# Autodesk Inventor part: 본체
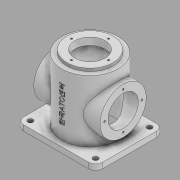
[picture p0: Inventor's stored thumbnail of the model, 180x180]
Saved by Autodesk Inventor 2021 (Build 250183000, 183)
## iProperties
Created: 2021-02
Part Number: 본체
Material: 알루미늄 6061
Document SubType Name: Modeling
Designer: 201-25
Density: 2.7 g/cm^3
Appearance: 기본값
Mass: 1239.52 g
Surface Area: 1098.82 cm^2
Volume: 459.08 cm^3
Author: 201-25
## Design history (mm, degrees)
sketch "스케치1"
  geometry: L1 (70, 60)-(-70, 60); L2 (-70, 60)-(-70, -60); L3 (-70, -60)-(70, -60); L4 (70, -60)-(70, 60); L5 (70, 60)-(-70, -60); L6 (-70, 60)-(70, -60); 1 further point
  constraints: 12 end point, 2 midpoint, 2 parallel, 1 horizontal, 1 perpendicular
  dimensions: "d0" = 140 distance of L3.end L2.end; "d1" = 120 distance of L2.end L1.end
extrude "돌출1" new body sketch "스케치1" distance "d2" = 10; taper "d3" = 0 deg
sketch "스케치2"
  geometry: C1 r 50 at (0, 0); 1 further point
  constraints: 1 centre point, 1 coincident
  dimensions: "d4" = 100 diameter of C1
extrude "돌출2" join sketch "스케치2" distance "d5" = 110; taper "d6" = 0 deg
sketch "스케치3"
  geometry: C1 r 41 at (0, 0); 1 further point
  constraints: 1 centre point, 1 coincident
  dimensions: "d7" = 82 diameter of C1
extrude "돌출3" join sketch "스케치3" distance "d8" = 5; taper "d9" = 0 deg
node "작업 평면1"
sketch "스케치4"
  geometry: L1 (0, 60)-(0, -60) reference; C1 r 41 at (60, 0); 2 further points
  constraints: 1 centre point, 1 horizontal alignment, 1 midpoint
  dimensions: "d11" = 82 diameter of C1; "d12" = 60 distance from line of L1 C1.centre
extrude "돌출4" join sketch "스케치4" stored distance "d13" = 5; taper "d14" = 0 deg
sketch "스케치5"
  geometry: C1 r 27 at (0, 0); 1 further point
  constraints: 1 centre point
  dimensions: "d15" = 54 diameter of C1
extrude "돌출5" cut sketch "스케치5" extent not by distance; stored distance "d16" = 0; taper "d17" = 0 deg
sketch "스케치6"
  geometry: C1 r 27 at (0, 0); 1 further point
  constraints: 1 centre point, 1 coincident
  dimensions: "d18" = 54 diameter of C1
extrude "돌출6" cut sketch "스케치6" extent not by distance; stored distance "d19" = 0; taper "d20" = 0 deg
sketch "스케치7"
  geometry: 1 further point
sketch "스케치8"
  geometry: A1 r 33 centre (0, 0) between (0, 33) and (-33, 0); 3 further points
  constraints: 4 point on circle, 1 centre point
  dimensions: "d21" = 66 diameter of A1
hole "구멍1" sketch "스케치8" at (0, 33), (-33, 0), (0, -33), (33, 0) diameter "d22" = 3.242; stored, may be unused: countersink angle "d26" = 90 deg, drill point angle "d28" = 118 deg; dims "d23" = 8, "d24" = 4, "d25" = 2, "d27" = 10
sketch "스케치9" dims "d16" = 0
  geometry: A1 r 33 centre (0, 0) between (33, 0) and (0, 33); 3 further points
  constraints: 4 point on circle, 1 centre point, 1 coincident
  dimensions: "d29" = 66 diameter of A1
hole "구멍2" sketch "스케치9" at (0, 33), (-33, 0), (0, -33), (33, 0) diameter "d30" = 3.242; stored, may be unused: countersink angle "d34" = 90 deg, drill point angle "d36" = 118 deg; dims "d16" = 0, "d31" = 8, "d32" = 4, "d33" = 2, "d35" = 10
sketch "스케치10"
  geometry: C1 r 42 at (0, 0); 1 further point
  constraints: 1 centre point, 1 coincident
  dimensions: "d37" = 84 diameter of C1
extrude "돌출7" cut sketch "스케치10" distance "d38" = 112; taper "d39" = 0 deg
fillet "모깎기1" dims "d40" = 12
sketch "스케치11"
  geometry: A1 r 12 centre (-58, 48) between (-58, 60) and (-70, 48) reference; A2 r 12 centre (58, 48) between (70, 48) and (58, 60) reference; A3 r 12 centre (58, -48) between (58, -60) and (70, -48) reference; A4 r 12 centre (-58, -48) between (-70, -48) and (-58, -60) reference; 5 further points
  constraints: 4 coincident
hole "구멍3" sketch "스케치11" at (-58, 48), (58, 48), (58, -48), (-58, -48) diameter "d41" = 9; stored, may be unused: countersink angle "d45" = 90 deg, drill point angle "d47" = 118 deg; dims "d42" = 8, "d43" = 4, "d44" = 2, "d46" = 10
node "작업 평면2"
sketch "스케치12"
  geometry: L1 (-58, 0)-(58, 0) reference; 3 further points
  constraints: 1 midpoint, 1 vertical alignment, 1 other
  dimensions: "d49" = 66 distance from line of L1 point (0, 66)
feature "엠보싱1" sketch "스케치12" dims "d50" = 0.5, "d51" = 0
node "솔리드1"
mirror "미러1"
mirror "미러2"
feature "A9D066F2-1C7D-4E18-AEED-F7BC21143FA4" dims "d41" = 9, "d42" = 8, "d43" = 4, "d44" = 2, "d45" = 90 deg, "d46" = 10, "d47" = 118 deg
other parameters: "d10" = 59
